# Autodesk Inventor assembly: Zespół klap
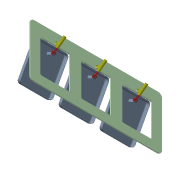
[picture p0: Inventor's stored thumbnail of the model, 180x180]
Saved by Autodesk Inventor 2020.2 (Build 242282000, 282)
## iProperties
Manager: www.cadconsulting.pl
Company: Fabian Stasiak CAD Consulting
Created: 2005-10
Part Number: Zespół klap
Document SubType Name: Assembly
Designer: F.Stasiak
Author: F.Stasiak
Subject: Zbiór ćwiczeń. Autodesk Inventor 2020. Kurs podstawowy
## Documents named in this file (4)
- C:\2020_Kurs_podstawowy\R6 Zespoły\Elastyczne\Zespół klap.iam
- C:\2020_Kurs_podstawowy\R6 Zespoły\Elastyczne\Obudowa_100E.ipt
- C:\2020_Kurs_podstawowy\R6 Zespoły\Elastyczne\Klapa_100E.ipt
- C:\2020_Kurs_podstawowy\R6 Zespoły\Elastyczne\Siłownik_100E.iam
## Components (7 placed, 3 different names)
1. Obudowa_100E:1 — Kąt:1, Wstaw:1, Wstaw:4, Wstaw:5, Wstaw:6, Wstaw:8, Wstaw:10
2. Klapa_100E:1 — Kąt:1, Wstaw:1, Wstaw:7
3. Klapa_100E:2 — Wstaw:4, Wstaw:9
4. Klapa_100E:3 — Wstaw:5, Wstaw:11
5. Siłownik_100E:1 [sub-assembly] — Wstaw:6, Wstaw:7
6. Siłownik_100E:2 [sub-assembly] — Wstaw:10, Wstaw:11
7. Siłownik_100E:3 [sub-assembly] — Wstaw:8, Wstaw:9
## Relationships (10: Insert 9, Angle 1)
- Kąt:1 [Angle]: Obudowa_100E:1 ↔ Klapa_100E:1
- Wstaw:1 [Insert]: Obudowa_100E:1 ↔ Klapa_100E:1
- Wstaw:4 [Insert]: Obudowa_100E:1 ↔ Klapa_100E:2
- Wstaw:5 [Insert]: Obudowa_100E:1 ↔ Klapa_100E:3
- Wstaw:6 [Insert]: Obudowa_100E:1 ↔ Siłownik_100E:1
- Wstaw:7 [Insert]: Klapa_100E:1 ↔ Siłownik_100E:1
- Wstaw:8 [Insert]: Obudowa_100E:1 ↔ Siłownik_100E:3
- Wstaw:9 [Insert]: Klapa_100E:2 ↔ Siłownik_100E:3
- Wstaw:10 [Insert]: Obudowa_100E:1 ↔ Siłownik_100E:2
- Wstaw:11 [Insert]: Klapa_100E:3 ↔ Siłownik_100E:2
